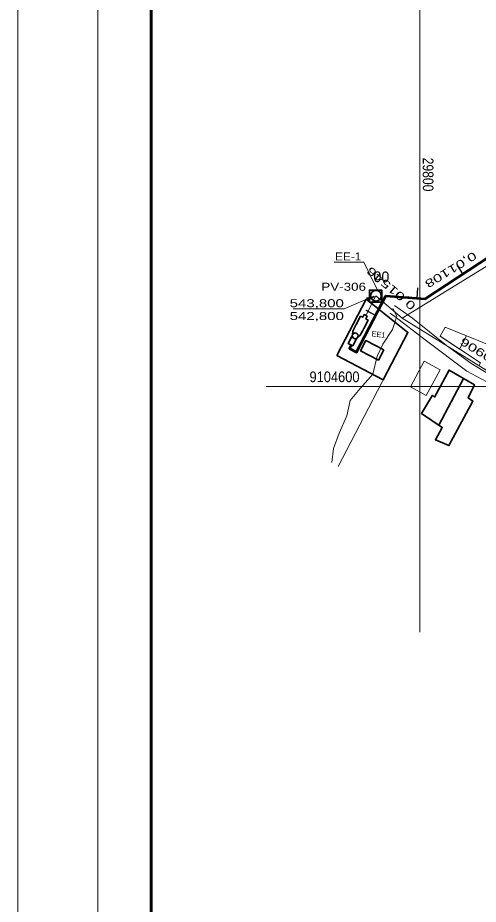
# Model space of a CAD drawing. Extents: x 949 to 2631, y -1701 to -513.
# Drawn here: x 948.9 to 1121.5, y -1014.6 to -682.4 of the extents above; entities that cross this region are included whole.
import ezdxf
from ezdxf.enums import TextEntityAlignment as Align

# ---------------------------------------------------------------- set-up
doc = ezdxf.new("R2010")
doc.units = 0
doc.header["$LTSCALE"] = 1.2
for name, color, linetype, lineweight in [('10', 7, 'Continuous', 13), ('15', 7, 'Continuous', 35), ('16', 7, 'Continuous', 13), ('17', 7, 'Continuous', 13), ('2', 7, 'Continuous', 13), ('28', 7, 'Continuous', 13), ('29', 7, 'Continuous', 25), ('4', 7, 'Continuous', 13), ('5', 7, 'Continuous', 13), ('6', 7, 'Continuous', 60), ('7', 7, 'Continuous', 35), ('9', 7, 'Continuous', 13)]:
    doc.layers.add(name, color=color, linetype=linetype, lineweight=lineweight)
doc.layers.add('30', color=7, linetype='Continuous')
doc.layers.add('63', color=7, linetype='Continuous')

msp = doc.modelspace()

# ---------------------------------------------------------------- hatches: boundary and pattern name
at = {"layer": '29'}
msp.add_hatch(color=256, dxfattribs=at).paths.add_polyline_path([(1082.774, -786.949), (1079.992, -788.393), (1079.637, -787.4)])

# ---------------------------------------------------------------- linework, layer by layer
at = {"layer": '10', "lineweight": 35}
msp.add_line((1106.662, -835.092), (1115.892, -817.562), dxfattribs=at)
at = {"layer": '10'}
for points in [[(1114.432, -806.602), (1107.192, -801.802), (1109.072, -798.352), (1117.012, -801.592)], [(1101.982, -823.942), (1107.122, -814.332), (1101.192, -811.162), (1096.062, -820.752)]]:
    msp.add_lwpolyline(points, close=True, dxfattribs=at)
at = {"layer": '10', "lineweight": 35}
msp.add_lwpolyline([(1100.132, -830.732), (1104.252, -823.912), (1105.112, -824.612), (1110.512, -814.442), (1120.042, -819.972), (1117.722, -824.842), (1119.442, -826.132), (1110.492, -842.752), (1105.382, -840.572), (1107.992, -835.982)], close=True, dxfattribs=at)
at = {"layer": '15'}
for p, q in [((1068.474, -809.04), (1079.482, -787.84)), ((1085.885, -818.081), (1068.474, -809.04))]:
    msp.add_line(p, q, dxfattribs=at)
msp.add_lwpolyline([(1085.885, -818.081), (1095.102, -800.332), (1079.482, -787.84)], dxfattribs=at)
at = {"layer": '16'}
for points in [[(1202.112, -855.382), (1187.532, -846.942), (1163.202, -834.882), (1127.632, -817.342), (1118.622, -811.832), (1109.572, -805.222), (1096.832, -794.962), (1090.042, -790.322)], [(1203.712, -862.782), (1193.662, -853.522), (1150.832, -832.832), (1117.142, -814.832), (1102.062, -803.452), (1089.692, -794.062), (1088.382, -793.152)]]:
    msp.add_lwpolyline(points, dxfattribs=at)
at = {"layer": '17'}
for p, q in [((1099.562, -912.671), (1099.562, -607.115)), ((1228.032, -820.632), (1041.978, -820.632))]:
    msp.add_line(p, q, dxfattribs=at)
at = {"layer": '2', "lineweight": 35}
msp.add_lwpolyline([(1086.056, -806.902), (1084.074, -810.718), (1077.374, -807.238), (1079.356, -803.422), (1086.056, -806.902)], close=True, dxfattribs=at)
at = {"layer": '28'}
for points in [[(1228.032, -722.015), (1213.354, -729.079), (1142.284, -764.629), (1093.004, -794.959)], [(1195.217, -912.671), (1196.314, -907.439), (1206.944, -863.359), (1149.214, -829.919), (1093.004, -794.959), (1083.134, -786.589)]]:
    msp.add_lwpolyline(points, dxfattribs=at)
at = {"layer": '28', "lineweight": 35}
msp.add_lwpolyline([(1085.277, -789.049), (1080.65, -789.049), (1080.65, -784.465), (1085.277, -784.465)], close=True, dxfattribs=at)
at = {"layer": '29'}
for p, q in [((1115.733, -778.426), (1113.633, -775.225)), ((1098.521, -787.504), (1098.804, -783.686)), ((1082.898, -793.954), (1079.501, -792.189)), ((1082.998, -793.954), (1079.6, -792.189))]:
    msp.add_line(p, q, dxfattribs=at)
at = {"layer": '29', "lineweight": 13}
for p, q in [((1082.326, -786.728), (1071.235, -791.566)), ((1071.235, -791.566), (1052.123, -791.566))]:
    msp.add_line(p, q, dxfattribs=at)
at = {"layer": '29', "lineweight": 53}
msp.add_lwpolyline([(1073.88, -805.132), (1073.202, -806.436), (1075.81, -807.79), (1086.799, -786.637), (1101.557, -787.729), (1138.256, -763.647), (1228.052, -719.585), (1284.057, -691.479), (1304.502, -688.949), (1348.513, -782.198), (1360.795, -834.118)], dxfattribs=at)
at = {"layer": '29'}
for points in [[(1086.799, -786.637), (1101.557, -787.729), (1138.256, -763.647), (1228.052, -719.585), (1284.057, -691.479), (1304.502, -688.949), (1348.513, -782.198), (1360.795, -834.118), (1364.521, -833.237)], [(1073.88, -805.132), (1073.202, -806.436), (1075.81, -807.79), (1086.799, -786.637)]]:
    msp.add_lwpolyline(points, dxfattribs=at)
at = {"layer": '29', "lineweight": 13}
msp.add_lwpolyline([(1082.774, -786.949), (1079.992, -788.393), (1079.637, -787.4)], close=True, dxfattribs=at)
at = {"layer": '29', "lineweight": 35}
msp.add_circle((1083.134, -786.589), 2, dxfattribs=at)
at = {"layer": '4', "lineweight": 35}
msp.add_line((1076.427, -801.733), (1076.439, -801.771), dxfattribs=at)
for points in [[(1076.29, -802.151), (1077.22, -801.392), (1078.161, -799.581), (1078.365, -799.405), (1078.504, -799.139), (1078.53, -798.871), (1080.167, -795.72), (1079.346, -795.294), (1079.876, -794.273), (1078.722, -793.674), (1078.192, -794.695), (1077.371, -794.268), (1075.735, -797.419), (1075.531, -797.594), (1075.392, -797.861), (1075.366, -798.129), (1074.425, -799.94), (1074.339, -801.137)], [(1075.922, -802.536), (1074.426, -805.416), (1072.74, -804.54), (1074.236, -801.66)]]:
    msp.add_lwpolyline(points, dxfattribs=at)
msp.add_circle((1075.335, -801.606), 1.1, dxfattribs=at)
at = {"layer": '5'}
for p, q in [((948.926, -1700.728), (948.926, -512.728)), ((978.926, -1106.728), (978.926, -512.728))]:
    msp.add_line(p, q, dxfattribs=at)
for points in [[(948.926, -512.728), (948.926, -1700.728), (948.926, -512.728)], [(1066.542, -849.092), (1067.242, -843.882), (1069.342, -838.162), (1072.182, -831.612), (1073.522, -825.912), (1077.202, -821.362), (1081.932, -815.982), (1083.542, -809.262), (1085.692, -804.742), (1089.272, -799.272), (1090.972, -794.242), (1089.452, -791.332)]]:
    msp.add_lwpolyline(points, dxfattribs=at)
at = {"layer": '6'}
msp.add_line((998.926, -1680.728), (998.926, -532.728), dxfattribs=at)
at = {"layer": '7', "lineweight": 13}
msp.add_line((1083.134, -786.589), (1079.298, -793.973), dxfattribs=at)
at = {"layer": '9'}
for p, q in [((1114.432, -806.602), (1117.012, -801.592)), ((1106.662, -835.092), (1115.892, -817.562))]:
    msp.add_line(p, q, dxfattribs=at)
for points in [[(1067.474, -774.054), (1078.591, -774.054), (1083.53, -784.321)], [(1068.992, -850.612), (1095.102, -800.332), (1087.662, -794.382)]]:
    msp.add_lwpolyline(points, dxfattribs=at)
for points in [[(1107.192, -801.802), (1122.262, -811.802), (1121.632, -812.892), (1138.582, -821.922), (1180.422, -841.832), (1185.662, -825.632), (1179.552, -823.952), (1181.262, -819.812), (1172.912, -820.282), (1168.902, -820.362), (1165.282, -819.702), (1158.672, -817.792), (1159.222, -816.212), (1147.312, -813.042), (1133.092, -806.952), (1133.612, -805.862), (1126.832, -802.742), (1125.712, -805.152), (1109.072, -798.352)], [(1100.132, -830.732), (1104.252, -823.912), (1105.112, -824.612), (1110.512, -814.442), (1120.042, -819.972), (1117.722, -824.842), (1119.442, -826.132), (1110.492, -842.752), (1105.382, -840.572), (1107.992, -835.982)]]:
    msp.add_lwpolyline(points, close=True, dxfattribs=at)

# ---------------------------------------------------------------- texts
at = {"layer": '10', "width": 1.1}
msp.add_text('EE-1', height=3, dxfattribs=at).set_placement((1067.821, -773.385))
at = {"layer": '17', "width": 0.85}
msp.add_text('29800', height=4, rotation=270, dxfattribs=at).set_placement((1100.672, -734.88))
at = {"layer": '17', "width": 0.9}
msp.add_text('9104600', height=4, dxfattribs=at).set_placement((1058.23, -818.992))
at = {"layer": '2'}
msp.add_text('EE1', height=2, rotation=352.945, dxfattribs=at).set_placement((1083.97, -802.099), align=Align.CENTER)
at = {"layer": '29'}
for s, width, p in [('PV-306', 1.25, (1062.671, -784.748)), (' 543,800', 1.4, (1049.248, -790.912)), (' 542,800', 1.4, (1049.248, -795.702))]:
    msp.add_text(s, height=3, dxfattribs=dict(at, width=width)).set_placement(p)
at = {"layer": '30'}
for s, rotation, width, p in [('0,01108', 211.611, 1.5, (1119.66, -769.944)), ('0,01546', 139.701, 1.55, (1098.342, -790.012)), ('0,00906', 148.12, 1.5, (1134.326, -813.564))]:
    msp.add_text(s, height=3, rotation=rotation, dxfattribs=dict(at, width=width)).set_placement(p)
at = {"layer": '63'}
msp.add_text('00', height=4, rotation=359.192, dxfattribs=at).set_placement((1085.139, -781.528), align=Align.CENTER)

doc.saveas('drawing.dxf')
